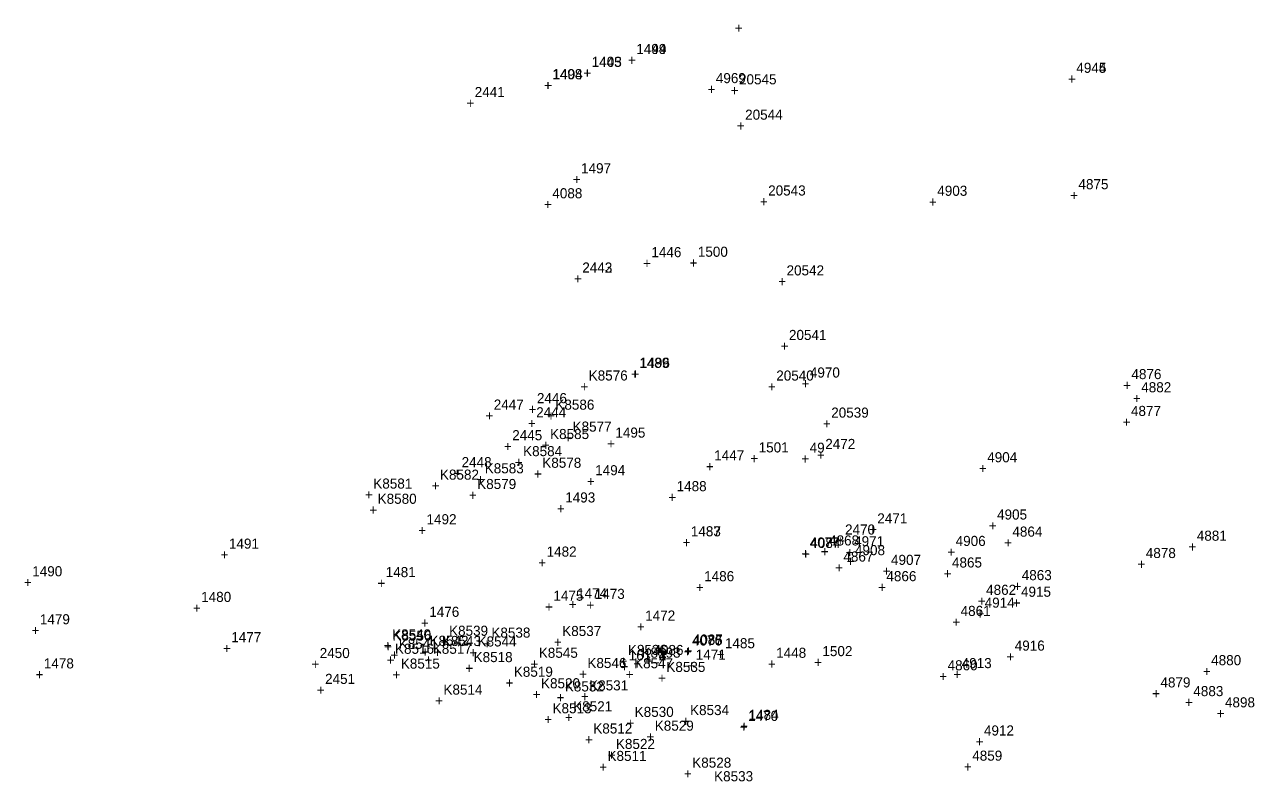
# Model space of a CAD drawing. Extents: x 1036751 to 1042192, y 772604 to 785439.
# Drawn here: x 1038273.7 to 1038578.5, y 778992.6 to 779180.2 of the extents above; entities that cross this region are included whole.
import ezdxf

# ---------------------------------------------------------------- set-up
doc = ezdxf.new("R2010")
doc.units = 0
for name, color, linetype in [('S_Control_Geodetic_ControlPoint', 7, 'Continuous'), ('S_Control_Temp_Traverse', 7, 'Continuous'), ('S_Drainage_CB', 7, 'Continuous'), ('S_Drainage_Ditch_Line', 7, 'Continuous'), ('S_Drainage_Sump', 7, 'Continuous'), ('S_Ground_Elevation', 7, 'Continuous'), ('S_Ground_LevelString', 7, 'Continuous'), ('S_Misc_MiscFeature', 7, 'Continuous'), ('S_Property_StoneWall', 7, 'Continuous'), ('S_Roadway_Centerline', 7, 'Continuous'), ('S_Roadway_Edge_Pavement', 7, 'Continuous'), ('S_Roadway_Edge_Shoulder', 7, 'Continuous'), ('S_Traffic_Sign_DoublePost', 7, 'Continuous'), ('S_Traffic_Sign_SinglePost', 7, 'Continuous'), ('S_Trees_Bush', 7, 'Continuous'), ('S_Trees_Conifer_NonPay', 7, 'Continuous'), ('S_Trees_Conifer_Pay', 7, 'Continuous'), ('S_Trees_Decid_Pay', 7, 'Continuous'), ('S_Utilities_GuyWire3', 7, 'Continuous'), ('S_Utilities_Pole_Power', 7, 'Continuous'), ('S_Utilities_UG_Water_Gate', 7, 'Continuous'), ('S_Utilities_UG_Water_Line', 7, 'Continuous')]:
    doc.layers.add(name, color=color, linetype=linetype)

msp = doc.modelspace()

# ---------------------------------------------------------------- texts
at = {"layer": 'S_Control_Geodetic_ControlPoint'}
for s, p in [('49', (1038468.29, 779074.05)), ('49', (1038468.29, 779074.05)), ('49', (1038468.29, 779074.05)), ('49', (1038468.29, 779074.05)), ('49', (1038468.29, 779074.05)), ('49', (1038468.29, 779074.05)), ('49', (1038468.29, 779074.05)), ('49', (1038468.29, 779074.05)), ('49', (1038468.29, 779074.05)), ('49', (1038468.29, 779074.05)), ('49', (1038468.29, 779074.05)), ('49', (1038468.29, 779074.05)), ('49', (1038468.29, 779074.05)), ('49', (1038468.29, 779074.05)), ('49', (1038468.29, 779074.05)), ('49', (1038468.29, 779074.05)), ('+', (1038466.22, 779071.3)), ('+', (1038466.22, 779071.3)), ('+', (1038466.22, 779071.3)), ('+', (1038466.22, 779071.3)), ('+', (1038466.22, 779071.3)), ('+', (1038466.22, 779071.3)), ('+', (1038466.22, 779071.3)), ('+', (1038466.22, 779071.3)), ('+', (1038466.22, 779071.3)), ('+', (1038466.22, 779071.3)), ('+', (1038466.22, 779071.3)), ('+', (1038466.22, 779071.3)), ('+', (1038466.22, 779071.3)), ('+', (1038466.22, 779071.3)), ('+', (1038466.22, 779071.3)), ('+', (1038466.22, 779071.3))]:
    msp.add_text(s, height=2.5, dxfattribs=at).set_placement(p)
at = {"layer": 'S_Control_Temp_Traverse'}
for s, p in [('161', (1038423.46, 779022.57)), ('161_1', (1038423.46, 779022.57)), ('161_3', (1038423.46, 779022.57)), ('161_2', (1038423.46, 779022.57)), ('161_4', (1038423.46, 779022.57)), ('+', (1038421.4, 779019.82)), ('+', (1038421.4, 779019.82)), ('+', (1038421.4, 779019.82)), ('+', (1038421.4, 779019.82)), ('+', (1038421.4, 779019.82))]:
    msp.add_text(s, height=2.5, dxfattribs=at).set_placement(p)
at = {"layer": 'S_Drainage_CB'}
for s, p in [('2442', (1038411.94, 779118.69)), ('+', (1038409.87, 779115.94))]:
    msp.add_text(s, height=2.5, dxfattribs=at).set_placement(p)
at = {"layer": 'S_Drainage_Ditch_Line'}
for s, p in [('4875', (1038534.9, 779139.36)), ('+', (1038532.83, 779136.61)), ('4876', (1038548.03, 779092.29)), ('+', (1038545.97, 779089.54))]:
    msp.add_text(s, height=2.5, dxfattribs=at).set_placement(p)
at = {"layer": 'S_Drainage_Sump'}
for s, p in [('2443', (1038411.95, 779118.71)), ('+', (1038409.89, 779115.96))]:
    msp.add_text(s, height=2.5, dxfattribs=at).set_placement(p)
at = {"layer": 'S_Ground_Elevation'}
for s, p in [('4969', (1038445.04, 779165.65)), ('4944', (1038534.38, 779168.21)), ('4945', (1038534.38, 779168.21)), ('+', (1038442.98, 779162.9)), ('+', (1038532.32, 779165.46)), ('+', (1038532.32, 779165.46)), ('4903', (1038499.92, 779137.73)), ('+', (1038497.85, 779134.98)), ('4970', (1038468.34, 779092.69)), ('K8576', (1038413.53, 779091.95)), ('+', (1038466.28, 779089.94)), ('4882', (1038550.46, 779089.03)), ('+', (1038411.47, 779089.2)), ('K8586', (1038405.27, 779084.71)), ('4877', (1038547.92, 779083.16)), ('+', (1038548.4, 779086.28)), ('+', (1038403.21, 779081.96)), ('+', (1038545.86, 779080.41)), ('K8585', (1038403.97, 779077.44)), ('K8577', (1038409.54, 779079.28)), ('+', (1038401.91, 779074.69)), ('+', (1038407.48, 779076.53)), ('K8584', (1038397.28, 779073.2)), ('4904', (1038512.29, 779071.68)), ('K8583', (1038387.77, 779068.94)), ('+', (1038395.22, 779070.45)), ('K8578', (1038402.03, 779070.32)), ('+', (1038510.23, 779068.93)), ('K8581', (1038360.15, 779065.16)), ('K8582', (1038376.67, 779067.37)), ('+', (1038385.71, 779066.19)), ('K8579', (1038385.9, 779065.05)), ('+', (1038399.97, 779067.57)), ('+', (1038358.09, 779062.41)), ('+', (1038374.61, 779064.62)), ('+', (1038383.84, 779062.3)), ('K8580', (1038361.23, 779061.39)), ('+', (1038359.17, 779058.64)), ('4905', (1038514.73, 779057.49)), ('+', (1038512.67, 779054.74)), ('4864', (1038518.53, 779053.25)), ('4868', (1038473.1, 779051.07)), ('4971', (1038479.31, 779050.86)), ('4906', (1038504.47, 779050.94)), ('+', (1038516.47, 779050.5)), ('4881', (1038564.23, 779052.24)), ('+', (1038471.04, 779048.32)), ('4867', (1038476.65, 779047.07)), ('+', (1038477.25, 779048.11)), ('4908', (1038479.53, 779048.66)), ('+', (1038502.41, 779048.19)), ('4878', (1038551.59, 779047.95)), ('+', (1038562.17, 779049.49)), ('+', (1038474.59, 779044.32)), ('+', (1038477.47, 779045.91)), ('4907', (1038488.45, 779046.25)), ('4865', (1038503.56, 779045.6)), ('+', (1038549.53, 779045.2)), ('+', (1038486.39, 779043.5)), ('4866', (1038487.31, 779042.21)), ('+', (1038501.49, 779042.85)), ('4863', (1038520.85, 779042.47)), ('+', (1038485.25, 779039.46)), ('4862', (1038512.02, 779038.82)), ('+', (1038518.79, 779039.72)), ('4915', (1038520.66, 779038.35)), ('+', (1038509.96, 779036.07)), ('4914', (1038511.66, 779035.64)), ('+', (1038518.6, 779035.6)), ('4861', (1038505.7, 779033.6)), ('+', (1038509.6, 779032.89)), ('+', (1038503.64, 779030.85)), ('K8541', (1038366.46, 779025.45)), ('K8542', (1038374.09, 779026.2)), ('K8543', (1038377.17, 779026.14)), ('K8544', (1038386, 779026.03)), ('4916', (1038519.11, 779025)), ('+', (1038364.4, 779022.7)), ('K8516', (1038365.53, 779024.21)), ('+', (1038372.03, 779023.45)), ('K8517', (1038374.9, 779024.21)), ('+', (1038375.11, 779023.39)), ('+', (1038383.94, 779023.28)), ('K8518', (1038385.01, 779022.15)), ('K8545', (1038401.17, 779023.22)), ('+', (1038363.46, 779021.46)), ('+', (1038372.84, 779021.46)), ('+', (1038382.95, 779019.4)), ('+', (1038399.1, 779020.47)), ('K8546', (1038413.21, 779020.68)), ('K8547', (1038424.78, 779020.63)), ('4860', (1038502.47, 779020.12)), ('4913', (1038505.96, 779020.66)), ('+', (1038517.05, 779022.25)), ('4880', (1038567.79, 779021.39)), ('K8519', (1038394.98, 779018.52)), ('+', (1038411.15, 779017.93)), ('+', (1038422.71, 779017.88)), ('+', (1038500.41, 779017.37)), ('+', (1038503.9, 779017.91)), ('4879', (1038555.22, 779015.88)), ('+', (1038565.73, 779018.64)), ('+', (1038392.92, 779015.77)), ('K8520', (1038401.71, 779015.66)), ('K8532', (1038407.62, 779014.88)), ('K8531', (1038413.65, 779015.14)), ('4883', (1038563.37, 779013.72)), ('+', (1038399.65, 779012.91)), ('+', (1038405.56, 779012.13)), ('K8521', (1038409.69, 779009.95)), ('+', (1038411.59, 779012.39)), ('+', (1038553.16, 779013.13)), ('+', (1038561.31, 779010.97)), ('4898', (1038571.21, 779010.94)), ('+', (1038407.63, 779007.2)), ('K8530', (1038424.93, 779008.57)), ('+', (1038569.15, 779008.19)), ('+', (1038422.87, 779005.82)), ('K8529', (1038429.91, 779005.15)), ('4912', (1038511.48, 779003.96)), ('K8522', (1038420.28, 779000.63)), ('+', (1038427.85, 779002.4)), ('+', (1038509.42, 779001.21)), ('4859', (1038508.58, 778997.72)), ('+', (1038418.22, 778997.88)), ('K8528', (1038439.19, 778995.99)), ('+', (1038506.52, 778994.97)), ('+', (1038437.13, 778993.24))]:
    msp.add_text(s, height=2.5, dxfattribs=at).set_placement(p)
at = {"layer": 'S_Ground_LevelString'}
for s, p in [('1489', (1038426.07, 779095.08)), ('+', (1038424.01, 779092.33)), ('1488', (1038435.32, 779064.52)), ('+', (1038433.26, 779061.77)), ('1487', (1038438.85, 779053.34)), ('+', (1038436.79, 779050.59)), ('1486', (1038442.15, 779042.2)), ('+', (1038440.09, 779039.45)), ('1485', (1038447.29, 779025.59)), ('+', (1038445.23, 779022.84)), ('1484', (1038453.16, 779007.83)), ('+', (1038451.09, 779005.08))]:
    msp.add_text(s, height=2.5, dxfattribs=at).set_placement(p)
at = {"layer": 'S_Misc_MiscFeature'}
for s, p in [('+', (1038449.73, 779178.07)), ('20545', (1038450.78, 779165.35)), ('+', (1038448.72, 779162.6)), ('20544', (1038452.3, 779156.59)), ('+', (1038450.24, 779153.84)), ('20543', (1038458.01, 779137.8)), ('+', (1038455.95, 779135.05)), ('20542', (1038462.56, 779118)), ('+', (1038460.5, 779115.25)), ('20541', (1038463.16, 779101.99)), ('+', (1038461.1, 779099.24)), ('20540', (1038460.01, 779091.93)), ('+', (1038457.95, 779089.18))]:
    msp.add_text(s, height=2.5, dxfattribs=at).set_placement(p)
at = {"layer": 'S_Property_StoneWall'}
for s, p in [('2446', (1038400.7, 779086.33)), ('2447', (1038390, 779084.74)), ('+', (1038398.64, 779083.58)), ('+', (1038387.94, 779081.99))]:
    msp.add_text(s, height=2.5, dxfattribs=at).set_placement(p)
at = {"layer": 'S_Roadway_Centerline'}
for s, p in [('1445', (1038414.25, 779169.67)), ('1403', (1038414.3, 779169.7)), ('+', (1038412.19, 779166.92)), ('+', (1038412.24, 779166.95)), ('1446', (1038429.06, 779122.52)), ('+', (1038427, 779119.77)), ('1447', (1038444.63, 779072.14)), ('+', (1038442.57, 779069.39)), ('1483', (1038438.84, 779053.32)), ('+', (1038436.78, 779050.57)), ('1482', (1038403.1, 779048.3)), ('+', (1038401.03, 779045.55)), ('1481', (1038363.23, 779043.22)), ('+', (1038361.17, 779040.47)), ('1480', (1038317.5, 779037.07)), ('1479', (1038277.52, 779031.53)), ('+', (1038315.44, 779034.32)), ('+', (1038275.46, 779028.78)), ('1448', (1038459.99, 779023.22)), ('+', (1038457.93, 779020.47))]:
    msp.add_text(s, height=2.5, dxfattribs=at).set_placement(p)
at = {"layer": 'S_Roadway_Edge_Pavement'}
for s, p in [('1444', (1038425.31, 779172.86)), ('1499', (1038425.33, 779172.87)), ('+', (1038423.25, 779170.11)), ('+', (1038423.27, 779170.12)), ('1498', (1038404.52, 779166.62)), ('1404', (1038404.6, 779166.61)), ('+', (1038402.46, 779163.87)), ('+', (1038402.53, 779163.86)), ('1497', (1038411.64, 779143.31)), ('+', (1038409.58, 779140.56)), ('1500', (1038440.58, 779122.62)), ('+', (1038438.52, 779119.87)), ('1496', (1038426.21, 779095.09)), ('+', (1038424.15, 779092.34)), ('1495', (1038420.14, 779077.8)), ('+', (1038418.08, 779075.05)), ('1501', (1038455.65, 779074.13)), ('+', (1038453.59, 779071.38)), ('1494', (1038415.14, 779068.47)), ('+', (1038413.08, 779065.72)), ('1493', (1038407.72, 779061.72)), ('+', (1038405.66, 779058.97)), ('1492', (1038373.34, 779056.32)), ('+', (1038371.28, 779053.57)), ('1491', (1038324.38, 779050.27)), ('+', (1038322.31, 779047.52)), ('1490', (1038275.63, 779043.43)), ('+', (1038273.57, 779040.68)), ('1475', (1038404.78, 779037.36)), ('1474', (1038410.66, 779037.97)), ('1473', (1038415.03, 779037.82)), ('+', (1038402.72, 779034.61)), ('+', (1038408.6, 779035.22)), ('+', (1038412.96, 779035.07)), ('1476', (1038374.02, 779033.37)), ('1472', (1038427.53, 779032.44)), ('+', (1038371.96, 779030.62)), ('+', (1038425.47, 779029.69)), ('1477', (1038324.96, 779027.09)), ('+', (1038322.9, 779024.34)), ('1471', (1038440.06, 779022.76)), ('1502', (1038471.45, 779023.63)), ('1478', (1038278.51, 779020.59)), ('+', (1038438, 779020.01)), ('+', (1038469.39, 779020.88)), ('+', (1038276.45, 779017.84)), ('1470', (1038453.04, 779007.58)), ('+', (1038450.98, 779004.83))]:
    msp.add_text(s, height=2.5, dxfattribs=at).set_placement(p)
at = {"layer": 'S_Roadway_Edge_Shoulder'}
for s, p in [('K8539', (1038378.93, 779028.68)), ('K8538', (1038389.42, 779028.22)), ('K8537', (1038406.97, 779028.62)), ('K8540', (1038364.81, 779027.78)), ('+', (1038376.87, 779025.93)), ('+', (1038387.36, 779025.47)), ('+', (1038404.91, 779025.87)), ('+', (1038362.75, 779025.03)), ('K8536', (1038423.25, 779023.93)), ('+', (1038421.19, 779021.18)), ('K8535', (1038432.78, 779019.72)), ('+', (1038430.72, 779016.97)), ('K8534', (1038438.65, 779009.02)), ('+', (1038436.59, 779006.27)), ('K8533', (1038444.61, 778992.62))]:
    msp.add_text(s, height=2.5, dxfattribs=at).set_placement(p)
at = {"layer": 'S_Traffic_Sign_DoublePost'}
for s, p in [('2444', (1038400.52, 779082.83)), ('2445', (1038394.58, 779077.15)), ('+', (1038398.46, 779080.08)), ('+', (1038392.52, 779074.4))]:
    msp.add_text(s, height=2.5, dxfattribs=at).set_placement(p)
at = {"layer": 'S_Traffic_Sign_SinglePost'}
for s, p in [('20539', (1038473.63, 779082.75)), ('+', (1038471.57, 779080)), ('2448', (1038382.04, 779070.47)), ('+', (1038379.98, 779067.72)), ('K8556', (1038364.89, 779027.48)), ('+', (1038362.83, 779024.73))]:
    msp.add_text(s, height=2.5, dxfattribs=at).set_placement(p)
at = {"layer": 'S_Trees_Bush'}
for s, p in [('K8512', (1038414.67, 779004.46)), ('+', (1038412.61, 779001.71))]:
    msp.add_text(s, height=2.5, dxfattribs=at).set_placement(p)
at = {"layer": 'S_Trees_Conifer_NonPay'}
for s, p in [('K8513', (1038404.57, 779009.47)), ('+', (1038402.51, 779006.73))]:
    msp.add_text(s, height=2.5, dxfattribs=at).set_placement(p)
at = {"layer": 'S_Trees_Conifer_Pay'}
for s, p in [('K8515', (1038366.97, 779020.54)), ('+', (1038364.91, 779017.79))]:
    msp.add_text(s, height=2.5, dxfattribs=at).set_placement(p)
at = {"layer": 'S_Trees_Decid_Pay'}
for s, p in [('2441', (1038385.28, 779162.2)), ('+', (1038383.22, 779159.45)), ('K8514', (1038377.54, 779014.1)), ('+', (1038375.48, 779011.35)), ('K8511', (1038418.2, 778997.66)), ('+', (1038416.14, 778994.91))]:
    msp.add_text(s, height=2.5, dxfattribs=at).set_placement(p)
at = {"layer": 'S_Utilities_GuyWire3'}
for s, p in [('2472', (1038472.15, 779074.98)), ('+', (1038470.08, 779072.23)), ('2471', (1038485.05, 779056.53)), ('+', (1038482.99, 779053.78)), ('2451', (1038348.2, 779016.75)), ('+', (1038346.14, 779014))]:
    msp.add_text(s, height=2.5, dxfattribs=at).set_placement(p)
at = {"layer": 'S_Utilities_Pole_Power'}
for s, p in [('2470', (1038477.06, 779053.77)), ('+', (1038475, 779051.02)), ('2450', (1038346.87, 779023.16)), ('+', (1038344.81, 779020.41))]:
    msp.add_text(s, height=2.5, dxfattribs=at).set_placement(p)
at = {"layer": 'S_Utilities_UG_Water_Gate'}
for s, p in [('K8593', (1038426.63, 779023.25)), ('+', (1038424.56, 779020.5))]:
    msp.add_text(s, height=2.5, dxfattribs=at).set_placement(p)
at = {"layer": 'S_Utilities_UG_Water_Line'}
for s, p in [('4088', (1038404.52, 779137.11)), ('+', (1038402.45, 779134.36)), ('4077', (1038468.32, 779050.56)), ('4084', (1038468.46, 779050.44)), ('+', (1038466.26, 779047.81)), ('+', (1038466.39, 779047.69)), ('4076', (1038439.13, 779026.27)), ('4085', (1038439.3, 779026.41)), ('4087', (1038439.32, 779026.51)), ('4086', (1038429.58, 779023.91)), ('+', (1038437.07, 779023.52)), ('+', (1038437.24, 779023.66)), ('+', (1038437.26, 779023.76)), ('+', (1038427.52, 779021.16))]:
    msp.add_text(s, height=2.5, dxfattribs=at).set_placement(p)

doc.saveas('drawing.dxf')
